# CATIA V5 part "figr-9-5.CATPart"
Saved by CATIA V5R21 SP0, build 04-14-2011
Part number: Part1
Bounding box of the stored display mesh (mm): x -71.324 to 69.61, y -211.059 to 0, z 0 to 45
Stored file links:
  D:\CATIA V5R21 E-RESOURCES\CATIA-V5R21\catia-v5r21-prt\c09-catia-v5r20-prt\c09-catia-v5r21-figr-9-5.CATPart
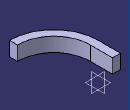
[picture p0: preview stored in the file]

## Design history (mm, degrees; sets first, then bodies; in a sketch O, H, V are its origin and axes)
Body1 (main body)
  Sketch1 on xy-plane, origin (0, 0, 0), H (1, 0, 0), V (0, 1, 0)
    line L1 (0, 0) -> (0, -70.1255)
    arc A1 centre (69.6095, -70.1255) radius 69.6095 from (0, -70.1255) to (69.6095, -139.7351) ccw
    vertical: L1 V
    tangency: A1 L1
  Sketch2 on zx-plane, origin (0, 0, 0), H (-1, 0, 0), V (0, 0, 1)
    point P1 (46.3244, 0)
    line L1 (46.3244, 0) -> (71.3244, 0)
    line L2 (71.3244, 0) -> (71.3244, 45)
    line L3 (71.3244, 45) -> (46.3244, 45)
    line L4 (46.3244, 45) -> (46.3244, 0)
    length L3 = 25
    length L2 = 45
    coincidence: P1 H
    horizontal: L1 H, L3 H
    vertical: L2 V, L4 V
  Rib1: profile Sketch2, centre curve Sketch1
